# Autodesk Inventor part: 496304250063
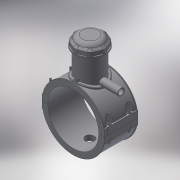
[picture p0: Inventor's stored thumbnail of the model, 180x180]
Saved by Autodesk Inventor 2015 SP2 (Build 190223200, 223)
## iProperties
Created: 2017-07
Part Number: 496304250063
Material: Generic
Description: PLASSON TAPPING SADDLE 250x63
Document SubType Name: Modeling
Designer: KIM
Mass: 2061.44 g
Surface Area: 4112.74 cm^2
Volume: 2061.44 cm^3
Density: 1 g/cm^3
Appearance: Default
Author: KIM
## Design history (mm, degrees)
derived "496304.ipt"
feature "Solid1::496304.ipt"
feature "Solid2::496304.ipt"
feature "Solid4::496304.ipt"
feature "Solid5::496304.ipt"
tag "TaggingFeature1" dims "d2" = 327.6
body "Solid1"
body "Solid2"
other parameters: "d3" = 62.5, "d4" = 176, "d5" = 0, "d6" = 0.1, "d8" = 0, "d19" = 6, "d20" = 6, "d21" = 105.6, "d23" = 0, "d24" = 52.8, "d26" = 0, "d29" = 3, "d30" = 83.33333, "d31" = 6, "d32" = 0, "d33" = 0, "d34" = 0.6, "d40" = 148.2, "d43" = 0, "d45" = 0, "d47" = 248.1, "d70" = 15, "d72" = 0, "d73" = 6, "d75" = 5, "d76" = 0, "d77" = 12.5, "d78" = 155, "d79" = 15, "d80" = 70.4, "d82" = 5 deg, "d84" = 4, "d85" = 14, "d86" = 0, "d87" = 3, "d88" = 0, "d89" = 1, "d90" = 1, "d91" = 140.8, "d92" = 0, "d93" = 0.5, "d94" = 131.57895, "d96" = 290.7, "d97" = 3.52, "d98" = 0, "d102" = 2.5, "d120" = 140 deg, "d121" = 24.228, "d122" = 20 deg, "d124" = 171, "d126" = 0, "d143" = 257.5, "d145" = 26.92308, "d149" = 3.75, "d150" = 29.61538, "d153" = 176, "d154" = 0, "d156" = 142.5, "d157" = 160 deg, "d159" = 7, "d161" = 3.75, "d162" = 105.6, "d163" = 0, "d164" = 125, "d167" = 25, "d168" = 139.02439, "d170" = 3.75, "d172" = 0, "d173" = 1, "d175" = 125, "d176" = 20 deg, "d177" = 17.5, "d178" = 35, "d180" = 0, "d183" = 14, "d184" = 14, "d185" = 57.2, "d186" = 57.2, "d187" = 142.5, "d188" = 10.5, "d189" = 17.5, "d190" = 0, "d191" = 213.75, "d193" = 7, "d194" = 6.16, "d195" = 90 deg, "d197" = 0, "d199" = 0, "d200" = 17.5, "d202" = 0, "d203" = 177, "d204" = 95, "d206" = 85, "d207" = 132.75, "d208" = 138.06, "d209" = 164.61, "d210" = 86, "d213" = 29.25, "d216" = 0, "d217" = 25, "d218" = 25, "d219" = 5, "d224" = 0, "d230" = 5, "d233" = 6, "d236" = 126, "d237" = 52.8, "d238" = 6.02433, "d240" = 52.8, "d241" = 52.8, "d242" = 52.8, "d243" = 6, "d244" = 52.8, "d245" = 52.8, "d246" = 52.8, "d247" = 6, "d248" = 6, "d249" = 6, "d251" = 52.8, "d253" = 6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
